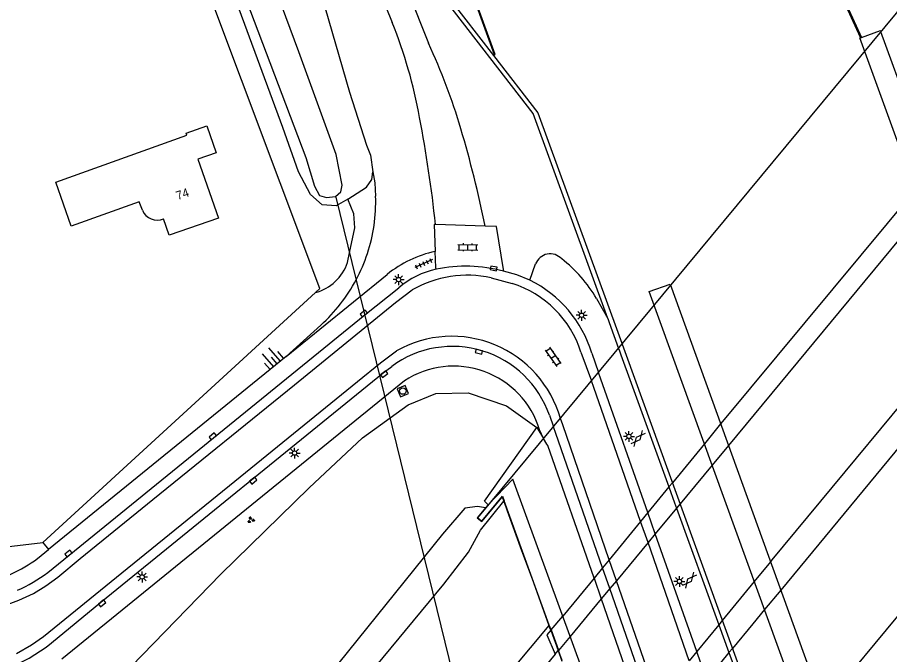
# Model space of a CAD drawing. Extents: x 135990 to 139000, y 393500 to 396000.
# Drawn here: x 136244.8 to 136345.5, y 395330 to 395403.6 of the extents above; entities that cross this region are included whole.
import ezdxf

# ---------------------------------------------------------------- set-up
doc = ezdxf.new("R2010")
doc.units = 0
for name, color, linetype in [('gg-afsc-erfafscheiding', 7, 'Continuous'), ('gg-afsc-muur', 7, 'Continuous'), ('gg-anno-huisnummerreeks BGT', 7, 'Continuous'), ('gg-bbg-hoofdgebouw', 7, 'Continuous'), ('gg-knt-BGT kruinlijn', 7, 'Continuous'), ('gg-knt-bovenkant onderkant talud', 7, 'Continuous'), ('gg-knt-bronhoudergrens niveau 01', 7, 'Continuous'), ('gg-knt-onverhard', 7, 'Continuous'), ('gg-knt-verharding', 7, 'Continuous'), ('gg-knt-verharding nz', 7, 'Continuous'), ('gg-kwrk-duiker nz buis', 7, 'Continuous'), ('gg-kwrk-kunstwerk niveau 01', 7, 'Continuous'), ('gt-grn-groengrens', 7, 'Continuous'), ('gt-grn-weggrens', 7, 'Continuous'), ('gt-symb-gesloten verharding', 7, 'Continuous'), ('gt-symb-groenvak', 7, 'Continuous'), ('gt-symb-klinker verharding', 7, 'Continuous'), ('gt-symb-kolk', 7, 'Continuous'), ('gt-symb-lichtmast', 7, 'Continuous'), ('gt-symb-rioolschacht', 7, 'Continuous'), ('gt-symb-talud symbool', 7, 'Continuous'), ('gt-symb-tegel verharding', 7, 'Continuous'), ('gx-grn-maaiveld', 7, 'Continuous')]:
    doc.layers.add(name, color=color, linetype=linetype)

# ---------------------------------------------------------------- blocks, each defined once
blk = doc.blocks.new('gt0-LMAST')
at = {"layer": 'gt-symb-lichtmast'}
for p, q in [((-0.18, 0.17), (-0.45, 0.44)), ((-0.01, 0.25), (-0.01, 0.62)), ((0.17, 0.17), (0.44, 0.44)), ((-0.26, 0), (-0.63, 0)), ((-0.18, -0.18), (-0.45, -0.45)), ((-0.01, -0.25), (-0.01, -0.63)), ((0.44, -0.45), (0.17, -0.18)), ((0.24, 0), (0.62, 0))]:
    blk.add_line(p, q, dxfattribs=at)
blk.add_circle((-0.01, 0), 0.25, dxfattribs=at)
blk = doc.blocks.new('gt0-GESVH1')
at = {"layer": 'gt-symb-gesloten verharding'}
for p, q in [((-0.99, -0.26), (0.01, 0.24)), ((0.01, -0.26), (-0.99, 0.24)), ((0.01, 0.24), (1.01, -0.26)), ((1.01, 0.24), (0.01, -0.26))]:
    blk.add_line(p, q, dxfattribs=at)
blk = doc.blocks.new('gt0-KOLK')
at = {"layer": 'gt-symb-kolk'}
blk.add_lwpolyline([(0, 0), (0.38, 0), (0.38, 0.4), (-0.38, 0.4), (-0.38, 0), (0, 0)], dxfattribs=at)
blk = doc.blocks.new('gt0-TALUD_1')
at = {"layer": 'gt-symb-talud symbool'}
for p, q in [((-1, -1), (-1, 0)), ((-0.5, -2), (-0.5, 0)), ((0, -1), (0, 0)), ((0.5, -2), (0.5, 0)), ((1, -1), (1, 0))]:
    blk.add_line(p, q, dxfattribs=at)
blk = doc.blocks.new('gt0-TEG1')
at = {"layer": 'gt-symb-tegel verharding'}
for p, q in [((-1.12, 0), (1.12, 0)), ((-0.9, -0.25), (-0.9, 0.25)), ((-0.45, -0.25), (-0.45, 0.25)), ((0, -0.25), (0, 0.25)), ((0.45, -0.25), (0.45, 0.25)), ((0.9, -0.25), (0.9, 0.25))]:
    blk.add_line(p, q, dxfattribs=at)
blk = doc.blocks.new('gt0-KL1')
at = {"layer": 'gt-symb-klinker verharding'}
for p, q in [((-1.15, 0.3), (1.15, 0.3)), ((-1, -0.3), (-1, 0.3)), ((-0.5, 0.3), (-0.5, 0.45)), ((0, -0.3), (0, 0.3)), ((0.5, 0.3), (0.5, 0.45)), ((1, -0.3), (1, 0.3)), ((-1.15, -0.3), (1.15, -0.3)), ((-0.5, -0.45), (-0.5, -0.3)), ((0.5, -0.45), (0.5, -0.3))]:
    blk.add_line(p, q, dxfattribs=at)
blk = doc.blocks.new('gt0-RS')
at = {"layer": 'gt-symb-rioolschacht'}
blk.add_lwpolyline([(-0.5, -0.5), (0.5, -0.5), (0.5, 0.5), (-0.5, 0.5)], close=True, dxfattribs=at)
blk.add_circle((0, 0), 0.375, dxfattribs=at)
blk = doc.blocks.new('gt0-GRVAK')
at = {"layer": 'gt-symb-groenvak'}
for p, q in [((-0.11, 0.19), (-0.23, 0.24)), ((-0.18, 0.15), (0.09, 0.15)), ((-0.09, 0.21), (-0.16, 0.32)), ((-0.05, 0.21), (-0.05, 0.39)), ((0, 0.21), (0.06, 0.32)), ((0.01, 0.19), (0.13, 0.24)), ((0.26, -0.05), (0.2, 0.06)), ((0.3, -0.05), (0.3, 0.13)), ((0.35, -0.05), (0.41, 0.06)), ((-0.25, -0.23), (-0.36, -0.18)), ((-0.32, -0.26), (-0.05, -0.26)), ((-0.23, -0.21), (-0.29, -0.09)), ((-0.18, -0.2), (-0.18, -0.02)), ((-0.14, -0.21), (-0.07, -0.09)), ((-0.12, -0.23), (0, -0.18)), ((0.24, -0.07), (0.12, -0.02)), ((0.17, -0.11), (0.44, -0.11)), ((0.37, -0.07), (0.49, -0.02))]:
    blk.add_line(p, q, dxfattribs=at)

msp = doc.modelspace()

# ---------------------------------------------------------------- linework, layer by layer
at = {"layer": 'gg-afsc-erfafscheiding'}
msp.add_line((136247.714, 395342.965), (136279.205, 395371.825), dxfattribs=at)
for points in [[(136279.205, 395371.825), (136279.691, 395372.271), (136266.101, 395408.62)], [(136207.631, 395358.241), (136207.39, 395357.903), (136229.306, 395341.209), (136234.303, 395341.382), (136247.714, 395342.965)]]:
    msp.add_lwpolyline(points, dxfattribs=at)
at = {"layer": 'gg-afsc-muur'}
msp.add_line((136342.152, 395401.33), (136322.977, 395443.213), dxfattribs=at)
msp.add_lwpolyline([(136299.894, 395399.297), (136293.033, 395418.219), (136286.952, 395434.933), (136281.088, 395450.963), (136274.631, 395468.663), (136268.917, 395484.409), (136261.555, 395504.825)], dxfattribs=at)
at = {"layer": 'gg-bbg-hoofdgebouw'}
msp.add_lwpolyline([(136259.221, 395381.33), (136258.871, 395382.28), (136251.011, 395379.49), (136249.241, 395384.56), (136264.371, 395389.97), (136264.281, 395390.22), (136266.651, 395391.06), (136267.741, 395387.95), (136265.611, 395387.2), (136268.011, 395380.4), (136262.331, 395378.44), (136261.659, 395380.33)], dxfattribs=at)
msp.add_arc((136260.953, 395382.08), 1.888, 203.42861, 291.96723, dxfattribs=at)
at = {"layer": 'gg-knt-BGT kruinlijn'}
for p, q in [((136296.463, 395346.944), (136293.862, 395343.949)), ((136297.902, 395347.118), (136296.463, 395346.944)), ((136293.862, 395343.949), (136274.643, 395320.124))]:
    msp.add_line(p, q, dxfattribs=at)
at = {"layer": 'gg-knt-bovenkant onderkant talud'}
msp.add_line((136303.971, 395373.235), (136304.62, 395375.125), dxfattribs=at)
for centre, radius, start, end in [((136306.303, 395374.485), 1.801, 42.57655, 159.17049), ((136297.945, 395363.101), 15.893, 30.3556, 52.45855)]:
    msp.add_arc(centre, radius, start, end, dxfattribs=at)
at = {"layer": 'gg-knt-bronhoudergrens niveau 01'}
msp.add_line((136297.946, 395345.834), (136364.721, 395426.333), dxfattribs=at)
at = {"layer": 'gg-knt-onverhard'}
for points in [[(136252.31, 395500), (136269.99, 395449.905), (136278.6, 395426.465), (136288.07, 395402.984)], [(136255.48, 395500), (136260.32, 395485.784), (136272.94, 395450.874), (136287.551, 395412.405), (136292.242, 395400.59)]]:
    msp.add_lwpolyline(points, dxfattribs=at)
for centre, radius, start, end in [((136235.486, 395381.877), 56.662, 10.32727, 21.87015), ((136230.507, 395371.47), 68.258, 16.39093, 25.25271), ((136142.103, 395363.599), 151.814, 6.08365, 10.79585), ((136167.248, 395352.578), 134.277, 11.55994, 16.50775)]:
    msp.add_arc(centre, radius, start, end, dxfattribs=at)
at = {"layer": 'gg-knt-verharding'}
for p, q in [((136298.802, 395379.486), (136293.062, 395379.688)), ((136282.909, 395375.3), (136283.139, 395376.41)), ((136275.808, 395364.428), (136287.49, 395373.917)), ((136299.476, 395373.533), (136301.899, 395372.863)), ((136279.84, 395368.074), (136275.808, 395364.428)), ((136275.808, 395364.428), (136248.378, 395342.147)), ((136309.852, 395364.936), (136311.083, 395361.616)), ((136311.092, 395364.82), (136311.882, 395362.576)), ((136289.468, 395361.63), (136249.912, 395329.52)), ((136306.217, 395357.664), (136306.68, 395356.327)), ((136305.526, 395354.996), (136305.081, 395355.991)), ((136247.112, 395341.119), (136248.378, 395342.147))]:
    msp.add_line(p, q, dxfattribs=at)
for points in [[(136293.062, 395379.688), (136292.901, 395379.694), (136293.022, 395376.572)], [(136300.895, 395374.301), (136300.926, 395374.481), (136300.112, 395379.44), (136298.802, 395379.486)], [(136293.139, 395374.525), (136293.094, 395374.712), (136293.022, 395376.572)], [(136303.971, 395373.235), (136302.465, 395373.86), (136300.895, 395374.301)], [(136241.662, 395335.262), (136243.426, 395335.728), (136244.974, 395336.324), (136246.65, 395337.093), (136248.065, 395337.967), (136249.448, 395338.964), (136252.06, 395341.116), (136260.443, 395347.94), (136276.773, 395361.189), (136288.432, 395370.681), (136290.371, 395372.145)], [(136248.291, 395339.501), (136284.913, 395369.257), (136288.83, 395372.374)], [(136244.677, 395330.146), (136246.407, 395331.176), (136247.825, 395332.138), (136256.87, 395339.47), (136269.908, 395350.04), (136284.063, 395361.561), (136286.705, 395363.693), (136287.63, 395364.416), (136288.573, 395365.101)], [(136248.742, 395331.387), (136254.442, 395336.102), (136287.023, 395362.557), (136288.006, 395363.305)]]:
    msp.add_lwpolyline(points, dxfattribs=at)
for centre, radius, start, end in [((136265.146, 395382.301), 21.014, 352.50446, 1.7284), ((136266.636, 395382.511), 19.568, 331.92363, 351.32735), ((136295.906, 395363.472), 13.414, 102.41617, 128.85978), ((136277.809, 395377.025), 5.384, 285.03199, 341.31394), ((136295.236, 395364.933), 9.819, 102.33146, 130.72416), ((136296.77, 395360.728), 13.088, 78.06685, 119.26844), ((136266.654, 395382.51), 19.552, 312.40975, 331.90102), ((136298.324, 395361.323), 12.081, 17.40203, 72.78558), ((136297.986, 395360.95), 13.665, 16.4517, 64.0259), ((136294.954, 395353.745), 13.025, 15.81391, 119.33108), ((136295.024, 395353.747), 11.858, 19.2901, 126.28834), ((136295.155, 395352.941), 10.384, 17.07972, 123.20354), ((136237.041, 395354.777), 16.97, 282.73546, 306.40317), ((136236.99, 395354.889), 19.092, 294.14974, 306.2937), ((136236.884, 395346.115), 18.908, 234.73328, 308.8379)]:
    msp.add_arc(centre, radius, start, end, dxfattribs=at)
at = {"layer": 'gg-knt-verharding nz'}
for p, q in [((136368.796, 395334.929), (136344.481, 395401.92)), ((136312.146, 395361.833), (136311.882, 395362.576)), ((136311.344, 395360.868), (136311.083, 395361.616)), ((136317.576, 395346.426), (136312.146, 395361.833)), ((136316.74, 395345.408), (136311.344, 395360.868)), ((136307.747, 395356.536), (136307.486, 395357.295)), ((136313.097, 395340.972), (136307.747, 395356.536)), ((136306.946, 395355.572), (136306.68, 395356.327)), ((136312.353, 395340.066), (136306.946, 395355.572)), ((136318.44, 395343.976), (136317.576, 395346.426)), ((136320.892, 395346.931), (136325.774, 395333.49)), ((136317.595, 395342.958), (136316.74, 395345.408)), ((136323.231, 395330.386), (136318.44, 395343.976)), ((136322.356, 395329.318), (136317.595, 395342.958)), ((136313.94, 395338.554), (136313.097, 395340.972)), ((136313.194, 395337.655), (136312.353, 395340.066)), ((136311.363, 395338.86), (136312.2, 395336.457)), ((136318.711, 395324.87), (136313.94, 395338.554)), ((136317.968, 395323.963), (136313.194, 395337.655)), ((136312.2, 395336.457), (136316.972, 395322.747)), ((136325.774, 395333.49), (136326.944, 395330.269)), ((136324.369, 395327.158), (136323.231, 395330.386)), ((136326.944, 395330.269), (136331.827, 395316.826))]:
    msp.add_line(p, q, dxfattribs=at)
for points in [[(136314.198, 395365.359), (136314.299, 395365.082), (136314.465, 395364.626)], [(136314.465, 395364.626), (136315.645, 395361.376), (136320.002, 395349.38)], [(136320.002, 395349.38), (136320.672, 395347.536), (136320.892, 395346.931)]]:
    msp.add_lwpolyline(points, dxfattribs=at)
at = {"layer": 'gg-kwrk-duiker nz buis'}
msp.add_line((136281.565, 395382.836), (136319.613, 395227.541), dxfattribs=at)
at = {"layer": 'gg-kwrk-kunstwerk niveau 01'}
for p, q in [((136325.976, 395356.655), (136324.103, 395354.375)), ((136324.103, 395354.375), (136320.412, 395349.879)), ((136326.879, 395354.159), (136325.003, 395351.893)), ((136320.002, 395349.38), (136317.576, 395346.426)), ((136320.412, 395349.879), (136320.002, 395349.38)), ((136300.787, 395348.313), (136300.979, 395347.785)), ((136306.2, 395333.437), (136300.979, 395347.785)), ((136321.301, 395347.424), (136320.892, 395346.931)), ((136317.576, 395346.426), (136316.74, 395345.408)), ((136320.892, 395346.931), (136318.44, 395343.976)), ((136316.74, 395345.408), (136313.097, 395340.972)), ((136318.44, 395343.976), (136317.595, 395342.958)), ((136317.595, 395342.958), (136313.94, 395338.554)), ((136313.097, 395340.972), (136312.353, 395340.066)), ((136331.729, 395340.756), (136329.866, 395338.483)), ((136312.353, 395340.066), (136311.363, 395338.86)), ((136311.363, 395338.86), (136307.753, 395334.464)), ((136313.94, 395338.554), (136313.194, 395337.655)), ((136329.866, 395338.483), (136326.175, 395333.978)), ((136313.194, 395337.655), (136312.2, 395336.457)), ((136332.914, 395337.48), (136331.047, 395335.225)), ((136312.2, 395336.457), (136308.605, 395332.125)), ((136306.398, 395332.893), (136307.753, 395334.464)), ((136306.398, 395332.893), (136306.2, 395333.437)), ((136325.774, 395333.49), (136323.231, 395330.386)), ((136326.175, 395333.978), (136325.774, 395333.49)), ((136306.398, 395332.893), (136307.244, 395330.566)), ((136308.605, 395332.125), (136307.265, 395330.51)), ((136307.265, 395330.51), (136307.244, 395330.566)), ((136307.692, 395329.337), (136307.265, 395330.51)), ((136323.231, 395330.386), (136322.356, 395329.318)), ((136326.944, 395330.269), (136324.369, 395327.158)), ((136327.344, 395330.752), (136326.944, 395330.269))]:
    msp.add_line(p, q, dxfattribs=at)
for points in [[(136348.428, 395383.66), (136326.2, 395356.928), (136325.976, 395356.655)], [(136349.306, 395381.245), (136347.639, 395379.231), (136326.879, 395354.159)], [(136354.18, 395367.84), (136331.906, 395340.973), (136331.729, 395340.756)], [(136355.36, 395364.595), (136354.144, 395363.12), (136332.914, 395337.48)], [(136325.003, 395351.893), (136322.037, 395348.311), (136321.301, 395347.424)], [(136337.774, 395324.048), (136340.068, 395326.834), (136360.256, 395351.13)], [(136297.946, 395345.834), (136298.406, 395345.452), (136300.787, 395348.313)], [(136331.047, 395335.225), (136329.69, 395333.586), (136327.344, 395330.752)]]:
    msp.add_lwpolyline(points, dxfattribs=at)
at = {"layer": 'gt-grn-groengrens'}
msp.add_line((136247.714, 395342.965), (136248.378, 395342.147), dxfattribs=at)
at = {"layer": 'gt-grn-weggrens'}
msp.add_arc((136296.531, 395357.581), 17.281, 75.37174, 101.31968, dxfattribs=at)
at = {"layer": 'gx-grn-maaiveld'}
for p, q in [((136292.973, 395407.955), (136299.759, 395399.198)), ((136342.229, 395401.269), (136342.145, 395401.238)), ((136299.847, 395399.28), (136299.759, 395399.198)), ((136283.631, 395380.913), (136282.939, 395382.597)), ((136311.659, 395371.133), (136312.941, 395368.819)), ((136304.764, 395356.245), (136305.526, 395354.996)), ((136305.546, 395354.964), (136305.526, 395354.996)), ((136305.924, 395354.342), (136305.546, 395354.964)), ((136299.134, 395347.339), (136301.993, 395350.286)), ((136326.206, 395283.778), (136301.993, 395350.286)), ((136298.839, 395346.984), (136299.134, 395347.339)), ((136298.839, 395346.984), (136297.902, 395347.118)), ((136306.361, 395332.849), (136306.163, 395333.393)), ((136306.361, 395332.849), (136307.208, 395330.521)), ((136306.858, 395330.088), (136307.208, 395330.521)), ((136307.208, 395330.521), (136307.655, 395329.293))]:
    msp.add_line(p, q, dxfattribs=at)
for points in [[(136299.847, 395399.28), (136299.941, 395399.314), (136293.08, 395418.236), (136286.999, 395434.95), (136281.135, 395450.98), (136274.678, 395468.68), (136268.964, 395484.426), (136261.598, 395504.88), (136261.646, 395504.898), (136260.041, 395509.349), (136259.993, 395509.334), (136254.233, 395525.069), (136247.945, 395542.323), (136241.554, 395559.99), (136234.053, 395580.83), (136226.487, 395601.747), (136221.073, 395616.708), (136214.518, 395634.98), (136206.192, 395658.269), (136198.931, 395678.51), (136193.504, 395693.382)], [(136190.897, 395584.584), (136190.937, 395584.26), (136191.394, 395583.3), (136195.045, 395580.243), (136199.962, 395575.992), (136213.858, 395565.103), (136218.652, 395560.964), (136221.928, 395557.524), (136224.529, 395553.561), (136226.083, 395550.242), (136227.156, 395547.569), (136229.727, 395540.355), (136238.057, 395515.441), (136250.482, 395482.708), (136265.547, 395444.086), (136269.179, 395432.872), (136275.497, 395420.05), (136279.918, 395406.148), (136283.146, 395394.967), (136285.104, 395388.821), (136285.551, 395387.696), (136285.829, 395385.747)], [(136257.151, 395503.25), (136261.505, 395504.846), (136268.87, 395484.392), (136274.584, 395468.646), (136281.042, 395450.946), (136286.905, 395434.916), (136292.986, 395418.202), (136299.847, 395399.28)], [(136322.932, 395443.192), (136342.106, 395401.309), (136342.145, 395401.238)], [(136322.977, 395443.213), (136323.023, 395443.234), (136342.229, 395401.269)], [(136262.958, 395427.353), (136278.098, 395387.396), (136279.111, 395384.099), (136279.661, 395383.029), (136280.497, 395382.794), (136281.502, 395382.924), (136282.149, 395383.432), (136282.277, 395384.219), (136281.588, 395387.769), (136277.288, 395399.593), (136264.908, 395432.991)], [(136282.939, 395382.597), (136281.582, 395381.831), (136279.96, 395381.933), (136278.616, 395383.124), (136277.235, 395385.739), (136275.455, 395390.875), (136270.133, 395405.259), (136266.662, 395414.874), (136265.39, 395417.73)], [(136312.941, 395368.819), (136304.354, 395392.501), (136293.661, 395406.3)], [(136342.229, 395401.269), (136344.427, 395402.069), (136344.481, 395401.92)], [(136369.361, 395333.499), (136367.008, 395332.561), (136342.049, 395401.203), (136342.145, 395401.238)], [(136299.759, 395399.198), (136304.888, 395392.579), (136314.116, 395367.25), (136338.976, 395298.657), (136346.802, 395277.114), (136352.5, 395261.797), (136359.689, 395264.341), (136359.884, 395263.54), (136361.246, 395259.835), (136361.527, 395259.101), (136355.02, 395256.723), (136355.04, 395256.648)], [(136282.939, 395382.597), (136285.087, 395383.974), (136285.73, 395384.857), (136285.829, 395385.747)], [(136285.829, 395385.747), (136286.046, 395384.497), (136286.15, 395382.935)], [(136283.139, 395376.41), (136283.74, 395379.304), (136283.631, 395380.913)], [(136345.031, 395304.132), (136342.665, 395303.182), (136317.737, 395371.933), (136320.134, 395372.802), (136344.511, 395305.428), (136345.031, 395304.132)], [(136312.941, 395368.819), (136313.105, 395368.368), (136314.198, 395365.359)], [(136245.799, 395316.07), (136247.57, 395318.024), (136268.264, 395339.315), (136278.485, 395349.281), (136284.643, 395355.052), (136289.897, 395358.868), (136293.095, 395360.152), (136296.843, 395360.229), (136301.25, 395358.764), (136304.764, 395356.245)], [(136299.134, 395347.339), (136298.703, 395347.758), (136304.764, 395356.245)], [(136311.363, 395338.86), (136306.041, 395354.15), (136305.924, 395354.342)], [(136180.83, 395225.678), (136184.812, 395228.425), (136193.216, 395234.685), (136202.066, 395242), (136210.951, 395249.879), (136220.014, 395258.455), (136229.572, 395267.884), (136229.758, 395268.067), (136247.241, 395285.658), (136261.458, 395300.179), (136266.233, 395305.147), (136269.32, 395308.628), (136277.453, 395318.127), (136294.031, 395338.167), (136296.887, 395341.848), (136298.245, 395344.401), (136300.943, 395347.74)], [(136298.839, 395346.984), (136297.876, 395345.828), (136298.412, 395345.382), (136300.77, 395348.214), (136300.943, 395347.74)], [(136300.943, 395347.74), (136301.352, 395346.614), (136302.853, 395342.49), (136304.358, 395338.354), (136305.772, 395334.468), (136306.163, 395333.393)], [(136306.163, 395333.393), (136292.816, 395317.473), (136274.414, 395295.48), (136246.779, 395262.308), (136241.892, 395256.389), (136226.301, 395237.504), (136207.038, 395214.234), (136203.801, 395210.332)], [(136306.361, 395332.849), (136305.924, 395332.322), (136306.858, 395330.088)], [(136306.858, 395330.088), (136291.372, 395311.273), (136290.335, 395312.14), (136289.89, 395311.607), (136290.869, 395310.788), (136270.503, 395286.431), (136269.448, 395287.303), (136268.936, 395286.685), (136270.011, 395285.796), (136252.366, 395264.45), (136251.422, 395265.224), (136251.021, 395264.735), (136251.957, 395263.966), (136244.469, 395254.834), (136244.069, 395254.357), (136236.663, 395245.523), (136235.801, 395246.235), (136235.382, 395245.728), (136236.217, 395245.038), (136220.224, 395225.664), (136219.368, 395226.37), (136218.934, 395225.844), (136219.719, 395225.197), (136206.166, 395208.752)]]:
    msp.add_lwpolyline(points, dxfattribs=at)

# ---------------------------------------------------------------- block references
at = {"layer": 'gt-symb-gesloten verharding'}
for p, rotation in [((136316.442, 395354.964), 50.27513746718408), ((136322.387, 395338.628), 50.27513747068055)]:
    msp.add_blockref('gt0-GESVH1', p, dxfattribs=dict(at, rotation=rotation))
at = {"layer": 'gt-symb-groenvak'}
msp.add_blockref('gt0-GRVAK', (136271.74, 395345.568), dxfattribs=at)
at = {"layer": 'gt-symb-klinker verharding'}
for p, rotation in [((136296.799, 395377.049), -0.9166542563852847), ((136306.632, 395364.399), -54.68878656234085)]:
    msp.add_blockref('gt0-KL1', p, dxfattribs=dict(at, rotation=rotation))
at = {"layer": 'gt-symb-kolk'}
for p, rotation in [((136299.732, 395374.417), -11.07387114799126), ((136284.913, 395369.257), 38.5434627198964), ((136298.132, 395365.191), 164.81021282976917), ((136287.023, 395362.557), -142.7177448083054), ((136267.467, 395355.077), 38.99099404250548), ((136271.892, 395350.273), -141.0450397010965), ((136250.814, 395341.556), 39.03551289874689), ((136254.442, 395336.102), -140.9644871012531)]:
    msp.add_blockref('gt0-KOLK', p, dxfattribs=dict(at, rotation=rotation))
at = {"layer": 'gt-symb-lichtmast'}
for p in [(136288.809, 395373.323), (136309.939, 395369.202), (136315.405, 395355.22), (136276.813, 395353.297), (136259.206, 395338.999), (136321.225, 395338.476)]:
    msp.add_blockref('gt0-LMAST', p, dxfattribs=at)
at = {"layer": 'gt-symb-rioolschacht', "rotation": 113.20611458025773}
msp.add_blockref('gt0-RS', (136289.3, 395360.452), dxfattribs=at)
at = {"layer": 'gt-symb-talud symbool', "xscale": 1.0003719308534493, "yscale": 1.000371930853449, "rotation": -138.5662292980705}
msp.add_blockref('gt0-TALUD_1', (136274.735, 395363.598), dxfattribs=at)
at = {"layer": 'gt-symb-tegel verharding', "rotation": -156.04914468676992}
msp.add_blockref('gt0-TEG1', (136291.686, 395375.166), dxfattribs=at)

# ---------------------------------------------------------------- texts
at = {"layer": 'gg-anno-huisnummerreeks BGT'}
msp.add_text('74', height=1, rotation=19, dxfattribs=at).set_placement((136263.305, 395382.479))

doc.saveas('drawing.dxf')
